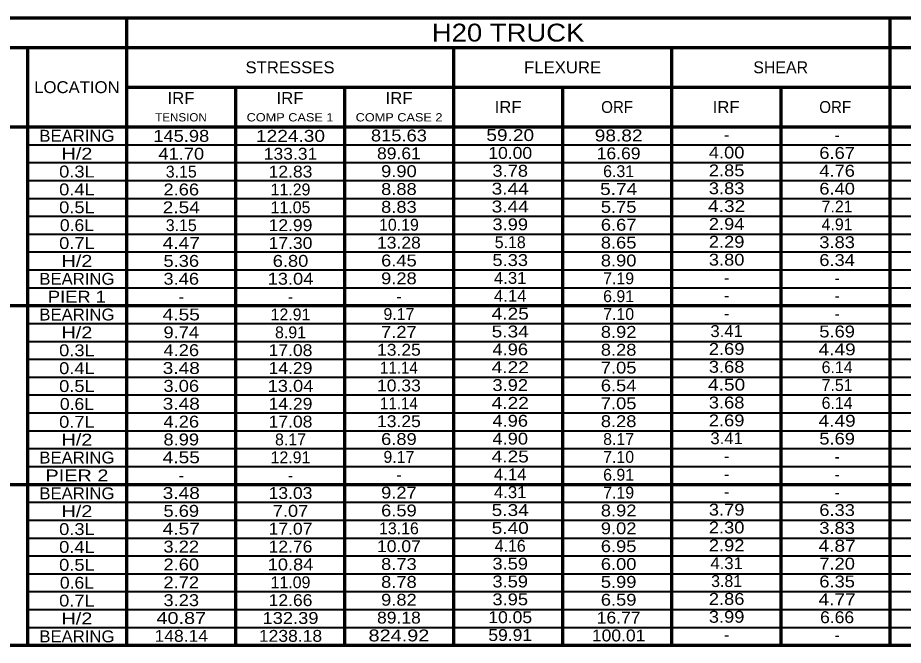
# Model space of a CAD drawing. Extents: x -2055 to -1915, y -81 to 6.
# Drawn here: x -2006.24 to -1961.57, y -25.85 to 5.78 of the extents above; entities that cross this region are included whole.
import ezdxf
from ezdxf.enums import TextEntityAlignment as Align

# ---------------------------------------------------------------- set-up
doc = ezdxf.new("R2010")
doc.units = 0
doc.header["$LTSCALE"] = 0.24
doc.layers.add('1', color=7, linetype='Continuous', lineweight=70)
doc.layers.add('5', color=7, linetype='Continuous', lineweight=40)
doc.layers.add('21', color=7, linetype='Continuous')
doc.layers.add('9', color=7, linetype='Continuous')

msp = doc.modelspace()

# ---------------------------------------------------------------- linework, layer by layer
at = {"layer": '1'}
for p, q in [((-2009.7523, 5.7798), (-1923.7523, 5.7798)), ((-2000.7523, 5.7798), (-2000.7523, -25.8503)), ((-1962.2523, 5.7798), (-1962.2523, -25.8503)), ((-2009.7523, 4.2798), (-1923.7523, 4.2798)), ((-2005.7523, 4.2798), (-2005.7523, -25.8503)), ((-1984.2523, 4.2798), (-1984.2523, -25.8503)), ((-1973.2523, 4.2798), (-1973.2523, -25.8503)), ((-2000.7523, 2.2798), (-1923.7523, 2.2798)), ((-1995.2523, 2.2798), (-1995.2523, -25.8503)), ((-1989.7523, 2.2798), (-1989.7523, -25.8503)), ((-1978.7523, 2.2798), (-1978.7523, -25.8503)), ((-1967.7523, 2.2798), (-1967.7523, -25.8503)), ((-2009.7523, 0.2798), (-1923.7523, 0.2798)), ((-2009.7523, -8.7306), (-1923.7523, -8.7306)), ((-2009.7523, -17.741), (-1923.7523, -17.741)), ((-2009.7523, -25.8503), (-1923.7523, -25.8503))]:
    msp.add_line(p, q, dxfattribs=at)
at = {"layer": '5'}
for p, q in [((-2005.7523, -0.6212), (-1923.7523, -0.6212)), ((-2005.7523, -1.5222), (-1923.7523, -1.5222)), ((-2005.7523, -2.4232), (-1923.7523, -2.4232)), ((-2005.7523, -3.3243), (-1923.7523, -3.3243)), ((-2005.7523, -4.2253), (-1923.7523, -4.2253)), ((-2005.7523, -5.1264), (-1923.7523, -5.1264)), ((-2005.7523, -6.0274), (-1923.7523, -6.0274)), ((-2005.7523, -6.9285), (-1923.7523, -6.9285)), ((-2005.7523, -7.8295), (-1923.7523, -7.8295)), ((-2005.7523, -9.6316), (-1923.7523, -9.6316)), ((-2005.7523, -10.5327), (-1923.7523, -10.5327)), ((-2005.7523, -11.4337), (-1923.7523, -11.4337)), ((-2005.7523, -12.3347), (-1923.7523, -12.3347)), ((-2005.7523, -13.2357), (-1923.7523, -13.2357)), ((-2005.7523, -14.1368), (-1923.7523, -14.1368)), ((-2005.7523, -15.0378), (-1923.7523, -15.0378)), ((-2005.7523, -15.9389), (-1923.7523, -15.9389)), ((-2005.7523, -16.8399), (-1923.7523, -16.8399)), ((-2005.7523, -18.642), (-1923.7523, -18.642)), ((-2005.7523, -19.5431), (-1923.7523, -19.5431)), ((-2005.7523, -20.4441), (-1923.7523, -20.4441)), ((-2005.7523, -21.3452), (-1923.7523, -21.3452)), ((-2005.7523, -22.2462), (-1923.7523, -22.2462)), ((-2005.7523, -23.1472), (-1923.7523, -23.1472)), ((-2005.7523, -24.0482), (-1923.7523, -24.0482)), ((-2005.7523, -24.9493), (-1923.7523, -24.9493))]:
    msp.add_line(p, q, dxfattribs=at)

# ---------------------------------------------------------------- texts
at = {"layer": '1'}
for s, width, p in [('BEARING', 1.05, (-2003.252, -0.4707)), ('H/2', 1.25, (-2003.2522, -1.3717)), ('0.3L', 1.15, (-2003.2521, -2.2727)), ('0.4L', 1.15, (-2003.2521, -3.1738)), ('0.5L', 1.15, (-2003.2521, -4.0748)), ('0.6L', 1.1, (-2003.2522, -4.9758)), ('0.7L', 1.15, (-2003.2521, -5.8769)), ('H/2', 1.25, (-2003.2522, -6.7779)), ('BEARING', 1.05, (-2003.252, -7.679)), ('PIER 1', 1.15, (-2003.2522, -8.58)), ('BEARING', 1.05, (-2003.252, -9.4811)), ('H/2', 1.25, (-2003.2522, -10.3821)), ('0.3L', 1.15, (-2003.2521, -11.2832)), ('0.4L', 1.15, (-2003.2521, -12.1842)), ('0.5L', 1.15, (-2003.2521, -13.0853)), ('0.6L', 1.1, (-2003.2522, -13.9863)), ('0.7L', 1.15, (-2003.2521, -14.8873)), ('H/2', 1.25, (-2003.2522, -15.7883)), ('BEARING', 1.05, (-2003.252, -16.6894)), ('PIER 2', 1.25, (-2003.2522, -17.5904)), ('BEARING', 1.05, (-2003.252, -18.4915)), ('H/2', 1.25, (-2003.2522, -19.3925)), ('0.3L', 1.15, (-2003.2521, -20.2936)), ('0.4L', 1.15, (-2003.2521, -21.1946)), ('0.5L', 1.15, (-2003.2521, -22.0957)), ('0.6L', 1.1, (-2003.2522, -22.9967)), ('0.7L', 1.15, (-2003.2521, -23.8977)), ('H/2', 1.25, (-2003.2522, -24.7987)), ('BEARING', 1.05, (-2003.252, -25.6998))]:
    msp.add_text(s, height=0.6, dxfattribs=dict(at, width=width)).set_placement(p, align=Align.CENTER)
at = {"layer": '21'}
for s, width, p in [('STRESSES', 1.05, (-1992.5022, 2.9798)), ('FLEXURE', 1.05, (-1978.7521, 2.9798)), ('LOCATION', 1.05, (-2003.2522, 1.9798)), ('IRF', 1.05, (-1998.0021, 1.4298)), ('IRF', 1.05, (-1992.5021, 1.4298)), ('IRF', 1.05, (-1987.0021, 1.4298)), ('IRF', 1.05, (-1981.5021, 0.9798)), ('ORF', 0.95, (-1976.0022, 0.9798)), ('IRF', 1.05, (-1970.5021, 0.9798)), ('ORF', 0.95, (-1965.0022, 0.9798))]:
    msp.add_text(s, height=0.6, dxfattribs=dict(at, width=width)).set_placement(p, align=Align.CENTER)
msp.add_text('SHEAR', height=0.6, dxfattribs=at).set_placement((-1967.7522, 2.9798), align=Align.CENTER)
at = {"layer": '9'}
for s, height, width, p in [('H20 TRUCK', 0.9, 1.15, (-1981.502, 4.5798)), ('TENSION', 0.4167, 1.05, (-1998.0022, 0.5525)), ('COMP CASE 1', 0.4167, 1.15, (-1992.5022, 0.5525)), ('COMP CASE 2', 0.4167, 1.15, (-1987.0023, 0.5525)), ('145.98', 0.6, 1.15, (-1997.9884, -0.4763)), ('1224.30', 0.6, 1.2, (-1992.4781, -0.4763)), ('815.63', 0.6, 1.15, (-1987.0093, -0.4555)), ('59.20', 0.6, 1.2, (-1981.3951, -0.4347)), ('98.82', 0.6, 1.2, (-1975.9263, -0.4555)), ('41.70', 0.6, 1.15, (-1997.9884, -1.3763)), ('133.31', 0.6, 1.1, (-1992.4781, -1.3763)), ('89.61', 0.6, 1.1, (-1987.0094, -1.3555)), ('10.00', 0.6, 1.1, (-1981.3951, -1.3347)), ('16.69', 0.6, 1.1, (-1975.9264, -1.3555)), ('4.00', 0.6, 1.15, (-1970.4785, -1.3139)), ('6.67', 0.6, 1.15, (-1964.9057, -1.3347)), ('12.83', 0.6, 1.1, (-1992.4781, -2.2763)), ('9.90', 0.6, 1.15, (-1987.0093, -2.2555)), ('3.78', 0.6, 1.15, (-1981.3951, -2.2348)), ('2.85', 0.6, 1.15, (-1970.4785, -2.2139)), ('4.76', 0.6, 1.15, (-1964.9057, -2.2348)), ('2.66', 0.6, 1.15, (-1997.9884, -3.1763)), ('8.88', 0.6, 1.15, (-1987.0094, -3.1555)), ('3.44', 0.6, 1.2, (-1981.3951, -3.1347)), ('5.74', 0.6, 1.2, (-1975.9264, -3.1555)), ('3.83', 0.6, 1.15, (-1970.4785, -3.1139)), ('6.40', 0.6, 1.15, (-1964.9057, -3.1347)), ('2.54', 0.6, 1.2, (-1997.9885, -4.0763)), ('8.83', 0.6, 1.15, (-1987.0094, -4.0555)), ('3.44', 0.6, 1.2, (-1981.3951, -4.0347)), ('5.75', 0.6, 1.15, (-1975.9264, -4.0555)), ('4.32', 0.6, 1.2, (-1970.4784, -4.0139)), ('12.99', 0.6, 1.1, (-1992.4781, -4.9763)), ('3.99', 0.6, 1.15, (-1981.3951, -4.9348)), ('6.67', 0.6, 1.15, (-1975.9264, -4.9555)), ('2.94', 0.6, 1.15, (-1970.4784, -4.9139)), ('4.47', 0.6, 1.2, (-1997.9885, -5.8763)), ('17.30', 0.6, 1.1, (-1992.4781, -5.8763)), ('13.28', 0.6, 1.1, (-1987.0094, -5.8555)), ('8.65', 0.6, 1.15, (-1975.9263, -5.8555)), ('2.29', 0.6, 1.15, (-1970.4785, -5.8139)), ('3.83', 0.6, 1.15, (-1964.9057, -5.8347)), ('5.36', 0.6, 1.15, (-1997.9885, -6.7763)), ('6.80', 0.6, 1.15, (-1992.4781, -6.7763)), ('6.45', 0.6, 1.15, (-1987.0093, -6.7555)), ('5.33', 0.6, 1.15, (-1981.3951, -6.7348)), ('8.90', 0.6, 1.15, (-1975.9264, -6.7555)), ('3.80', 0.6, 1.15, (-1970.4784, -6.7139)), ('6.34', 0.6, 1.15, (-1964.9057, -6.7348)), ('3.46', 0.6, 1.15, (-1997.9885, -7.6763)), ('13.04', 0.6, 1.15, (-1992.4781, -7.6763)), ('9.28', 0.6, 1.15, (-1987.0093, -7.6555)), ('4.31', 0.6, 1.05, (-1981.3951, -7.6347)), ('4.14', 0.6, 1.05, (-1981.3951, -8.5347)), ('4.55', 0.6, 1.2, (-1997.9885, -9.4763)), ('4.25', 0.6, 1.2, (-1981.3951, -9.4347)), ('9.74', 0.6, 1.15, (-1997.9884, -10.3763)), ('7.27', 0.6, 1.15, (-1987.0094, -10.3555)), ('5.34', 0.6, 1.2, (-1981.3951, -10.3347)), ('8.92', 0.6, 1.15, (-1975.9263, -10.3555)), ('3.41', 0.6, 1.05, (-1970.4784, -10.3139)), ('5.69', 0.6, 1.15, (-1964.9057, -10.3347)), ('4.26', 0.6, 1.15, (-1997.9885, -11.2763)), ('17.08', 0.6, 1.1, (-1992.4781, -11.2763)), ('13.25', 0.6, 1.1, (-1987.0094, -11.2555)), ('4.96', 0.6, 1.15, (-1981.3951, -11.2348)), ('8.28', 0.6, 1.15, (-1975.9264, -11.2555)), ('2.69', 0.6, 1.15, (-1970.4784, -11.2139)), ('4.49', 0.6, 1.2, (-1964.9057, -11.2348)), ('3.48', 0.6, 1.2, (-1997.9885, -12.1763)), ('14.29', 0.6, 1.1, (-1992.4781, -12.1763)), ('11.14', 0.6, 0.95, (-1987.0093, -12.1555)), ('4.22', 0.6, 1.2, (-1981.3951, -12.1348)), ('7.05', 0.6, 1.15, (-1975.9263, -12.1555)), ('3.68', 0.6, 1.15, (-1970.4784, -12.1139)), ('3.06', 0.6, 1.15, (-1997.9884, -13.0763)), ('13.04', 0.6, 1.15, (-1992.4781, -13.0763)), ('10.33', 0.6, 1.1, (-1987.0093, -13.0555)), ('3.92', 0.6, 1.15, (-1981.3951, -13.0347)), ('6.54', 0.6, 1.15, (-1975.9263, -13.0555)), ('4.50', 0.6, 1.2, (-1970.4784, -13.0139)), ('3.48', 0.6, 1.2, (-1997.9885, -13.9763)), ('14.29', 0.6, 1.1, (-1992.4781, -13.9763)), ('11.14', 0.6, 0.95, (-1987.0093, -13.9555)), ('4.22', 0.6, 1.2, (-1981.3951, -13.9347)), ('7.05', 0.6, 1.15, (-1975.9263, -13.9555)), ('3.68', 0.6, 1.15, (-1970.4784, -13.9139)), ('4.26', 0.6, 1.15, (-1997.9885, -14.8763)), ('17.08', 0.6, 1.1, (-1992.4781, -14.8763)), ('13.25', 0.6, 1.1, (-1987.0094, -14.8555)), ('4.96', 0.6, 1.15, (-1981.3951, -14.8347)), ('8.28', 0.6, 1.15, (-1975.9264, -14.8555)), ('2.69', 0.6, 1.15, (-1970.4784, -14.8139)), ('4.49', 0.6, 1.2, (-1964.9057, -14.8347)), ('8.99', 0.6, 1.15, (-1997.9884, -15.7763)), ('6.89', 0.6, 1.15, (-1987.0093, -15.7555)), ('4.90', 0.6, 1.15, (-1981.3951, -15.7348)), ('3.41', 0.6, 1.05, (-1970.4784, -15.7139)), ('5.69', 0.6, 1.15, (-1964.9057, -15.7348)), ('4.55', 0.6, 1.2, (-1997.9885, -16.6763)), ('4.25', 0.6, 1.2, (-1981.3951, -16.6348)), ('4.14', 0.6, 1.05, (-1981.3951, -17.5347)), ('3.48', 0.6, 1.2, (-1997.9885, -18.4763)), ('13.03', 0.6, 1.1, (-1992.4781, -18.4763)), ('9.27', 0.6, 1.15, (-1987.0093, -18.4555)), ('4.31', 0.6, 1.05, (-1981.3951, -18.4348)), ('6.59', 0.6, 1.15, (-1987.0093, -19.3555)), ('5.34', 0.6, 1.2, (-1981.3951, -19.3347)), ('8.92', 0.6, 1.15, (-1975.9263, -19.3555)), ('3.79', 0.6, 1.15, (-1970.4784, -19.3139)), ('6.33', 0.6, 1.15, (-1964.9057, -19.3347)), ('5.69', 0.6, 1.15, (-1997.9884, -19.3763)), ('7.07', 0.6, 1.15, (-1992.4781, -19.3763)), ('5.40', 0.6, 1.2, (-1981.3951, -20.2347)), ('9.02', 0.6, 1.15, (-1975.9264, -20.2555)), ('2.30', 0.6, 1.15, (-1970.4784, -20.2139)), ('3.83', 0.6, 1.15, (-1964.9057, -20.2347)), ('4.57', 0.6, 1.2, (-1997.9885, -20.2763)), ('17.07', 0.6, 1.1, (-1992.4781, -20.2763)), ('10.07', 0.6, 1.1, (-1987.0094, -21.1555)), ('6.95', 0.6, 1.15, (-1975.9264, -21.1555)), ('2.92', 0.6, 1.15, (-1970.4784, -21.1139)), ('4.87', 0.6, 1.2, (-1964.9057, -21.1348)), ('3.22', 0.6, 1.15, (-1997.9885, -21.1763)), ('12.76', 0.6, 1.1, (-1992.4781, -21.1763)), ('3.59', 0.6, 1.15, (-1981.3951, -22.0347)), ('4.31', 0.6, 1.05, (-1970.4784, -22.0139)), ('7.20', 0.6, 1.15, (-1964.9057, -22.0347)), ('2.60', 0.6, 1.15, (-1997.9885, -22.0763)), ('10.84', 0.6, 1.15, (-1992.4781, -22.0763)), ('8.73', 0.6, 1.15, (-1987.0094, -22.0555)), ('6.00', 0.6, 1.15, (-1975.9263, -22.0555)), ('3.59', 0.6, 1.15, (-1981.3951, -22.9347)), ('6.35', 0.6, 1.15, (-1964.9057, -22.9347)), ('2.72', 0.6, 1.15, (-1997.9885, -22.9763)), ('8.78', 0.6, 1.15, (-1987.0094, -22.9555)), ('5.99', 0.6, 1.15, (-1975.9263, -22.9555)), ('3.95', 0.6, 1.15, (-1981.3951, -23.8347)), ('2.86', 0.6, 1.15, (-1970.4785, -23.8139)), ('3.23', 0.6, 1.15, (-1997.9885, -23.8763)), ('12.66', 0.6, 1.1, (-1992.4781, -23.8763)), ('9.82', 0.6, 1.15, (-1987.0093, -23.8555)), ('6.59', 0.6, 1.15, (-1975.9263, -23.8555)), ('4.77', 0.6, 1.2, (-1964.9057, -23.8347)), ('3.99', 0.6, 1.15, (-1970.4784, -24.7139)), ('40.87', 0.6, 1.25, (-1997.9884, -24.7763)), ('132.39', 0.6, 1.15, (-1992.4781, -24.7763)), ('89.18', 0.6, 1.1, (-1987.0093, -24.7555)), ('10.05', 0.6, 1.1, (-1981.3951, -24.7347)), ('16.77', 0.6, 1.1, (-1975.9264, -24.7555)), ('6.66', 0.6, 1.1, (-1964.9056, -24.7347)), ('148.14', 0.6, 1.1, (-1997.9884, -25.6763)), ('1238.18', 0.6, 1.1, (-1992.4781, -25.6763)), ('824.92', 0.6, 1.25, (-1987.0093, -25.6555)), ('59.91', 0.6, 1.1, (-1981.3951, -25.6348)), ('100.01', 0.6, 1.1, (-1975.9263, -25.6555))]:
    msp.add_text(s, height=height, dxfattribs=dict(at, width=width)).set_placement(p, align=Align.CENTER)
for s, p in [('-', (-1970.4784, -0.4139)), ('-', (-1964.9057, -0.4347)), ('3.15', (-1997.9885, -2.2763)), ('6.31', (-1975.9263, -2.2555)), ('11.29', (-1992.4781, -3.1763)), ('11.05', (-1992.4781, -4.0763)), ('7.21', (-1964.9057, -4.0347)), ('3.15', (-1997.9885, -4.9763)), ('10.19', (-1987.0093, -4.9555)), ('4.91', (-1964.9056, -4.9348)), ('5.18', (-1981.3951, -5.8347)), ('7.19', (-1975.9263, -7.6555)), ('-', (-1970.4784, -7.6139)), ('-', (-1964.9057, -7.6347)), ('6.91', (-1975.9263, -8.5555)), ('-', (-1997.9885, -8.5763)), ('-', (-1992.4781, -8.5763)), ('-', (-1987.0094, -8.5555)), ('-', (-1970.4784, -8.5139)), ('-', (-1964.9057, -8.5347)), ('12.91', (-1992.4781, -9.4763)), ('9.17', (-1987.0093, -9.4555)), ('7.10', (-1975.9263, -9.4555)), ('-', (-1970.4784, -9.4139)), ('-', (-1964.9057, -9.4347)), ('8.91', (-1992.4781, -10.3763)), ('6.14', (-1964.9056, -12.1348)), ('7.51', (-1964.9057, -13.0347)), ('6.14', (-1964.9056, -13.9347)), ('8.17', (-1992.4781, -15.7763)), ('8.17', (-1975.9263, -15.7555)), ('12.91', (-1992.4781, -16.6763)), ('9.17', (-1987.0093, -16.6555)), ('7.10', (-1975.9263, -16.6555)), ('-', (-1970.4784, -16.6139)), ('-', (-1964.9057, -16.6348)), ('6.91', (-1975.9263, -17.5555)), ('-', (-1997.9885, -17.5763)), ('-', (-1992.4781, -17.5763)), ('-', (-1987.0094, -17.5555)), ('-', (-1970.4784, -17.5139)), ('-', (-1964.9057, -17.5347)), ('7.19', (-1975.9263, -18.4555)), ('-', (-1970.4784, -18.4139)), ('-', (-1964.9057, -18.4348)), ('13.16', (-1987.0093, -20.2555)), ('4.16', (-1981.3951, -21.1348)), ('3.81', (-1970.4784, -22.9139)), ('11.09', (-1992.478, -22.9763)), ('-', (-1970.4784, -25.6139)), ('-', (-1964.9057, -25.6348))]:
    msp.add_text(s, height=0.6, dxfattribs=at).set_placement(p, align=Align.CENTER)

doc.saveas('drawing.dxf')
